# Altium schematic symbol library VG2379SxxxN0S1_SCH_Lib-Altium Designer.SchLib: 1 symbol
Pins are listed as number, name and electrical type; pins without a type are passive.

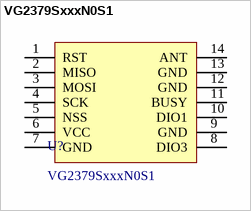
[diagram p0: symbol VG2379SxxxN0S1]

## VG2379SxxxN0S1
designator U?
footprint G237xNS1
footprint G237xNS1-TO
pins: 1 RST, 2 MISO, 3 MOSI, 4 SCK, 5 NSS, 6 VCC, 7 GND, 8 DIO3, 9 GND, 10 DIO1, 11 BUSY, 12 GND, 13 GND, 14 ANT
